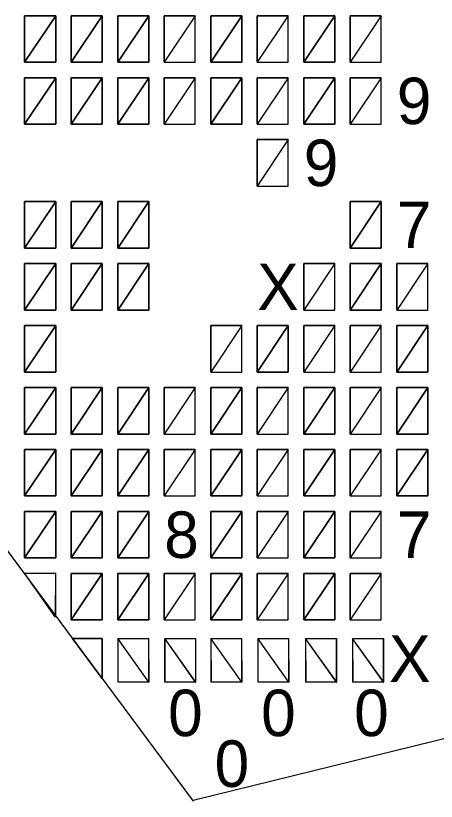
# Model space of a CAD drawing. Extents: x 0 to 34, y -1.2 to 22.
# Drawn here: x 3.4427 to 3.5971, y 4.3379 to 4.6264 of the extents above; entities that cross this region are included whole.
import ezdxf

# ---------------------------------------------------------------- set-up
doc = ezdxf.new("R2010")
doc.units = 0
doc.layers.add('Default', color=7, linetype='Continuous')

msp = doc.modelspace()

# ---------------------------------------------------------------- linework, layer by layer
at = {"layer": 'Default'}
for p, q in [((3.4574, 4.62644), (3.44602, 4.62644)), ((3.44602, 4.62644), (3.44602, 4.60937)), ((3.4574, 4.60937), (3.4574, 4.62644)), ((3.46309, 4.62644), (3.46309, 4.60937)), ((3.47447, 4.62644), (3.46309, 4.62644)), ((3.47447, 4.60937), (3.47447, 4.62644)), ((3.49154, 4.62644), (3.48016, 4.62644)), ((3.48016, 4.62644), (3.48016, 4.60937)), ((3.49154, 4.60937), (3.49154, 4.62644)), ((3.49723, 4.62644), (3.49723, 4.60937)), ((3.50861, 4.62644), (3.49723, 4.62644)), ((3.50861, 4.60937), (3.50861, 4.62644)), ((3.52568, 4.62644), (3.5143, 4.62644)), ((3.5143, 4.62644), (3.5143, 4.60937)), ((3.52568, 4.60937), (3.52568, 4.62644)), ((3.53137, 4.62644), (3.53137, 4.60937)), ((3.54276, 4.62644), (3.53137, 4.62644)), ((3.54276, 4.60937), (3.54276, 4.62644)), ((3.54845, 4.62644), (3.54845, 4.60937)), ((3.55983, 4.62644), (3.54845, 4.62644)), ((3.55983, 4.60937), (3.55983, 4.62644)), ((3.5769, 4.62644), (3.56552, 4.62644)), ((3.56552, 4.62644), (3.56552, 4.60937)), ((3.5769, 4.60937), (3.5769, 4.62644)), ((3.44602, 4.60937), (3.4574, 4.60937)), ((3.46309, 4.60937), (3.47447, 4.60937)), ((3.48016, 4.60937), (3.49154, 4.60937)), ((3.49723, 4.60937), (3.50861, 4.60937)), ((3.5143, 4.60937), (3.52568, 4.60937)), ((3.53137, 4.60937), (3.54276, 4.60937)), ((3.54845, 4.60937), (3.55983, 4.60937)), ((3.56552, 4.60937), (3.5769, 4.60937)), ((3.44602, 4.60368), (3.44602, 4.58661)), ((3.4574, 4.60368), (3.44602, 4.60368)), ((3.4574, 4.58661), (3.4574, 4.60368)), ((3.47447, 4.60368), (3.46309, 4.60368)), ((3.46309, 4.60368), (3.46309, 4.58661)), ((3.47447, 4.58661), (3.47447, 4.60368)), ((3.48016, 4.60368), (3.48016, 4.58661)), ((3.49154, 4.60368), (3.48016, 4.60368)), ((3.49154, 4.58661), (3.49154, 4.60368)), ((3.50861, 4.60368), (3.49723, 4.60368)), ((3.49723, 4.60368), (3.49723, 4.58661)), ((3.50861, 4.58661), (3.50861, 4.60368)), ((3.5143, 4.60368), (3.5143, 4.58661)), ((3.52568, 4.60368), (3.5143, 4.60368)), ((3.52568, 4.58661), (3.52568, 4.60368)), ((3.54276, 4.60368), (3.53137, 4.60368)), ((3.53137, 4.60368), (3.53137, 4.58661)), ((3.54276, 4.58661), (3.54276, 4.60368)), ((3.55983, 4.60368), (3.54845, 4.60368)), ((3.54845, 4.60368), (3.54845, 4.58661)), ((3.55983, 4.58661), (3.55983, 4.60368)), ((3.56552, 4.60368), (3.56552, 4.58661)), ((3.5769, 4.60368), (3.56552, 4.60368)), ((3.5769, 4.58661), (3.5769, 4.60368)), ((3.44602, 4.58661), (3.4574, 4.58661)), ((3.46309, 4.58661), (3.47447, 4.58661)), ((3.48016, 4.58661), (3.49154, 4.58661)), ((3.49723, 4.58661), (3.50861, 4.58661)), ((3.5143, 4.58661), (3.52568, 4.58661)), ((3.53137, 4.58661), (3.54276, 4.58661)), ((3.54845, 4.58661), (3.55983, 4.58661)), ((3.56552, 4.58661), (3.5769, 4.58661)), ((3.54276, 4.58092), (3.53137, 4.58092)), ((3.53137, 4.58092), (3.53137, 4.56385)), ((3.54276, 4.56385), (3.54276, 4.58092)), ((3.53137, 4.56385), (3.54276, 4.56385)), ((3.44602, 4.55816), (3.44602, 4.54109)), ((3.4574, 4.55816), (3.44602, 4.55816)), ((3.4574, 4.54109), (3.4574, 4.55816)), ((3.47447, 4.55816), (3.46309, 4.55816)), ((3.46309, 4.55816), (3.46309, 4.54109)), ((3.47447, 4.54109), (3.47447, 4.55816)), ((3.48016, 4.55816), (3.48016, 4.54109)), ((3.49154, 4.55816), (3.48016, 4.55816)), ((3.49154, 4.54109), (3.49154, 4.55816)), ((3.5769, 4.55816), (3.56552, 4.55816)), ((3.56552, 4.55816), (3.56552, 4.54109)), ((3.5769, 4.54109), (3.5769, 4.55816)), ((3.34772, 4.55371), (3.50785, 4.3379)), ((3.44602, 4.54109), (3.4574, 4.54109)), ((3.46309, 4.54109), (3.47447, 4.54109)), ((3.48016, 4.54109), (3.49154, 4.54109)), ((3.56552, 4.54109), (3.5769, 4.54109)), ((3.44602, 4.53539), (3.44602, 4.51832)), ((3.4574, 4.53539), (3.44602, 4.53539)), ((3.4574, 4.51832), (3.4574, 4.53539)), ((3.46309, 4.53539), (3.46309, 4.51832)), ((3.47447, 4.53539), (3.46309, 4.53539)), ((3.47447, 4.51832), (3.47447, 4.53539)), ((3.49154, 4.53539), (3.48016, 4.53539)), ((3.48016, 4.53539), (3.48016, 4.51832)), ((3.49154, 4.51832), (3.49154, 4.53539)), ((3.54845, 4.53539), (3.54845, 4.51832)), ((3.55983, 4.53539), (3.54845, 4.53539)), ((3.55983, 4.51832), (3.55983, 4.53539)), ((3.56552, 4.53539), (3.56552, 4.51832)), ((3.5769, 4.53539), (3.56552, 4.53539)), ((3.5769, 4.51832), (3.5769, 4.53539)), ((3.59397, 4.53539), (3.58259, 4.53539)), ((3.58259, 4.53539), (3.58259, 4.51832)), ((3.59397, 4.51832), (3.59397, 4.53539)), ((3.44602, 4.51832), (3.4574, 4.51832)), ((3.46309, 4.51832), (3.47447, 4.51832)), ((3.48016, 4.51832), (3.49154, 4.51832)), ((3.54845, 4.51832), (3.55983, 4.51832)), ((3.56552, 4.51832), (3.5769, 4.51832)), ((3.58259, 4.51832), (3.59397, 4.51832)), ((3.4574, 4.51263), (3.44602, 4.51263)), ((3.44602, 4.51263), (3.44602, 4.49556)), ((3.4574, 4.49556), (3.4574, 4.51263)), ((3.52568, 4.51263), (3.5143, 4.51263)), ((3.5143, 4.51263), (3.5143, 4.49556)), ((3.52568, 4.49556), (3.52568, 4.51263)), ((3.54276, 4.51263), (3.53137, 4.51263)), ((3.53137, 4.51263), (3.53137, 4.49556)), ((3.54276, 4.49556), (3.54276, 4.51263)), ((3.54845, 4.51263), (3.54845, 4.49556)), ((3.55983, 4.51263), (3.54845, 4.51263)), ((3.55983, 4.49556), (3.55983, 4.51263)), ((3.56552, 4.51263), (3.56552, 4.49556)), ((3.5769, 4.51263), (3.56552, 4.51263)), ((3.5769, 4.49556), (3.5769, 4.51263)), ((3.58259, 4.51263), (3.58259, 4.49556)), ((3.59397, 4.51263), (3.58259, 4.51263)), ((3.59397, 4.49556), (3.59397, 4.51263)), ((3.44602, 4.49556), (3.4574, 4.49556)), ((3.5143, 4.49556), (3.52568, 4.49556)), ((3.53137, 4.49556), (3.54276, 4.49556)), ((3.54845, 4.49556), (3.55983, 4.49556)), ((3.56552, 4.49556), (3.5769, 4.49556)), ((3.58259, 4.49556), (3.59397, 4.49556)), ((3.4574, 4.48987), (3.44602, 4.48987)), ((3.44602, 4.48987), (3.44602, 4.4728)), ((3.4574, 4.4728), (3.4574, 4.48987)), ((3.46309, 4.48987), (3.46309, 4.4728)), ((3.47447, 4.48987), (3.46309, 4.48987)), ((3.47447, 4.4728), (3.47447, 4.48987)), ((3.49154, 4.48987), (3.48016, 4.48987)), ((3.48016, 4.48987), (3.48016, 4.4728)), ((3.49154, 4.4728), (3.49154, 4.48987)), ((3.49723, 4.48987), (3.49723, 4.4728)), ((3.50861, 4.48987), (3.49723, 4.48987)), ((3.50861, 4.4728), (3.50861, 4.48987)), ((3.52568, 4.48987), (3.5143, 4.48987)), ((3.5143, 4.48987), (3.5143, 4.4728)), ((3.52568, 4.4728), (3.52568, 4.48987)), ((3.53137, 4.48987), (3.53137, 4.4728)), ((3.54276, 4.48987), (3.53137, 4.48987)), ((3.54276, 4.4728), (3.54276, 4.48987)), ((3.54845, 4.48987), (3.54845, 4.4728)), ((3.55983, 4.48987), (3.54845, 4.48987)), ((3.55983, 4.4728), (3.55983, 4.48987)), ((3.5769, 4.48987), (3.56552, 4.48987)), ((3.56552, 4.48987), (3.56552, 4.4728)), ((3.5769, 4.4728), (3.5769, 4.48987)), ((3.59397, 4.48987), (3.58259, 4.48987)), ((3.58259, 4.48987), (3.58259, 4.4728)), ((3.59397, 4.4728), (3.59397, 4.48987)), ((3.44602, 4.4728), (3.4574, 4.4728)), ((3.46309, 4.4728), (3.47447, 4.4728)), ((3.48016, 4.4728), (3.49154, 4.4728)), ((3.49723, 4.4728), (3.50861, 4.4728)), ((3.5143, 4.4728), (3.52568, 4.4728)), ((3.53137, 4.4728), (3.54276, 4.4728)), ((3.54845, 4.4728), (3.55983, 4.4728)), ((3.56552, 4.4728), (3.5769, 4.4728)), ((3.58259, 4.4728), (3.59397, 4.4728)), ((3.44602, 4.46711), (3.44602, 4.45004)), ((3.4574, 4.46711), (3.44602, 4.46711)), ((3.4574, 4.45004), (3.4574, 4.46711)), ((3.47447, 4.46711), (3.46309, 4.46711)), ((3.46309, 4.46711), (3.46309, 4.45004)), ((3.47447, 4.45004), (3.47447, 4.46711)), ((3.48016, 4.46711), (3.48016, 4.45004)), ((3.49154, 4.46711), (3.48016, 4.46711)), ((3.49154, 4.45004), (3.49154, 4.46711)), ((3.50861, 4.46711), (3.49723, 4.46711)), ((3.49723, 4.46711), (3.49723, 4.45004)), ((3.50861, 4.45004), (3.50861, 4.46711)), ((3.5143, 4.46711), (3.5143, 4.45004)), ((3.52568, 4.46711), (3.5143, 4.46711)), ((3.52568, 4.45004), (3.52568, 4.46711)), ((3.54276, 4.46711), (3.53137, 4.46711)), ((3.53137, 4.46711), (3.53137, 4.45004)), ((3.54276, 4.45004), (3.54276, 4.46711)), ((3.55983, 4.46711), (3.54845, 4.46711)), ((3.54845, 4.46711), (3.54845, 4.45004)), ((3.55983, 4.45004), (3.55983, 4.46711)), ((3.56552, 4.46711), (3.56552, 4.45004)), ((3.5769, 4.46711), (3.56552, 4.46711)), ((3.5769, 4.45004), (3.5769, 4.46711)), ((3.58259, 4.46711), (3.58259, 4.45004)), ((3.59397, 4.46711), (3.58259, 4.46711)), ((3.59397, 4.45004), (3.59397, 4.46711)), ((3.44602, 4.45004), (3.4574, 4.45004)), ((3.46309, 4.45004), (3.47447, 4.45004)), ((3.48016, 4.45004), (3.49154, 4.45004)), ((3.49723, 4.45004), (3.50861, 4.45004)), ((3.5143, 4.45004), (3.52568, 4.45004)), ((3.53137, 4.45004), (3.54276, 4.45004)), ((3.54845, 4.45004), (3.55983, 4.45004)), ((3.56552, 4.45004), (3.5769, 4.45004)), ((3.58259, 4.45004), (3.59397, 4.45004)), ((3.4574, 4.44435), (3.44602, 4.44435)), ((3.44602, 4.44435), (3.44602, 4.42728)), ((3.4574, 4.42728), (3.4574, 4.44435)), ((3.46309, 4.44435), (3.46309, 4.42728)), ((3.47447, 4.44435), (3.46309, 4.44435)), ((3.47447, 4.42728), (3.47447, 4.44435)), ((3.49154, 4.44435), (3.48016, 4.44435)), ((3.48016, 4.44435), (3.48016, 4.42728)), ((3.49154, 4.42728), (3.49154, 4.44435)), ((3.52568, 4.44435), (3.5143, 4.44435)), ((3.5143, 4.44435), (3.5143, 4.42728)), ((3.52568, 4.42728), (3.52568, 4.44435)), ((3.53137, 4.44435), (3.53137, 4.42728)), ((3.54276, 4.44435), (3.53137, 4.44435)), ((3.54276, 4.42728), (3.54276, 4.44435)), ((3.54845, 4.44435), (3.54845, 4.42728)), ((3.55983, 4.44435), (3.54845, 4.44435)), ((3.55983, 4.42728), (3.55983, 4.44435)), ((3.5769, 4.44435), (3.56552, 4.44435)), ((3.56552, 4.44435), (3.56552, 4.42728)), ((3.5769, 4.42728), (3.5769, 4.44435)), ((3.44602, 4.42728), (3.4574, 4.42728)), ((3.46309, 4.42728), (3.47447, 4.42728)), ((3.48016, 4.42728), (3.49154, 4.42728)), ((3.5143, 4.42728), (3.52568, 4.42728)), ((3.53137, 4.42728), (3.54276, 4.42728)), ((3.54845, 4.42728), (3.55983, 4.42728)), ((3.56552, 4.42728), (3.5769, 4.42728)), ((3.4574, 4.42159), (3.44602, 4.42159)), ((3.4574, 4.40547), (3.4574, 4.42159)), ((3.47447, 4.42159), (3.46309, 4.42159)), ((3.46309, 4.42159), (3.46309, 4.40452)), ((3.47447, 4.40452), (3.47447, 4.42159)), ((3.48016, 4.42159), (3.48016, 4.40452)), ((3.49154, 4.42159), (3.48016, 4.42159)), ((3.49154, 4.40452), (3.49154, 4.42159)), ((3.50861, 4.42159), (3.49723, 4.42159)), ((3.49723, 4.42159), (3.49723, 4.40452)), ((3.50861, 4.40452), (3.50861, 4.42159)), ((3.5143, 4.42159), (3.5143, 4.40452)), ((3.52568, 4.42159), (3.5143, 4.42159)), ((3.52568, 4.40452), (3.52568, 4.42159)), ((3.54276, 4.42159), (3.53137, 4.42159)), ((3.53137, 4.42159), (3.53137, 4.40452)), ((3.54276, 4.40452), (3.54276, 4.42159)), ((3.55983, 4.42159), (3.54845, 4.42159)), ((3.54845, 4.42159), (3.54845, 4.40452)), ((3.55983, 4.40452), (3.55983, 4.42159)), ((3.56552, 4.42159), (3.56552, 4.40452)), ((3.5769, 4.42159), (3.56552, 4.42159)), ((3.5769, 4.40452), (3.5769, 4.42159)), ((3.46309, 4.40452), (3.47447, 4.40452)), ((3.48016, 4.40452), (3.49154, 4.40452)), ((3.49723, 4.40452), (3.50861, 4.40452)), ((3.5143, 4.40452), (3.52568, 4.40452)), ((3.53137, 4.40452), (3.54276, 4.40452)), ((3.54845, 4.40452), (3.55983, 4.40452)), ((3.56552, 4.40452), (3.5769, 4.40452)), ((3.76865, 4.40245), (3.50784, 4.33819)), ((3.47449, 4.39766), (3.46362, 4.39766)), ((3.47447, 4.38287), (3.47447, 4.39766)), ((3.48016, 4.39766), (3.48016, 4.38175)), ((3.48017, 4.39766), (3.49153, 4.39766)), ((3.49154, 4.38175), (3.49154, 4.39766)), ((3.4974, 4.39766), (3.4974, 4.38175)), ((3.49741, 4.39766), (3.50877, 4.39766)), ((3.50878, 4.38175), (3.50878, 4.39766)), ((3.51433, 4.39766), (3.51433, 4.38175)), ((3.51434, 4.39766), (3.5257, 4.39766)), ((3.52571, 4.38175), (3.52571, 4.39766)), ((3.53157, 4.39766), (3.53157, 4.38175)), ((3.53158, 4.39766), (3.54294, 4.39766)), ((3.54295, 4.38175), (3.54295, 4.39766)), ((3.54913, 4.39766), (3.54913, 4.38175)), ((3.54914, 4.39766), (3.5605, 4.39766)), ((3.56051, 4.38175), (3.56051, 4.39766)), ((3.56637, 4.39766), (3.56637, 4.38175)), ((3.56638, 4.39766), (3.57774, 4.39766)), ((3.57775, 4.38175), (3.57775, 4.39766)), ((3.48016, 4.38175), (3.49154, 4.38175)), ((3.4974, 4.38175), (3.50878, 4.38175)), ((3.51433, 4.38175), (3.52571, 4.38175)), ((3.53157, 4.38175), (3.54295, 4.38175)), ((3.54913, 4.38175), (3.56051, 4.38175)), ((3.56637, 4.38175), (3.57775, 4.38175))]:
    msp.add_line(p, q, dxfattribs=at)
for points in [[(3.4574, 4.62644), (3.4574, 4.60937), (3.44602, 4.60937)], [(3.44602, 4.60937), (3.44602, 4.62644), (3.4574, 4.62644)], [(3.4574, 4.62644), (3.4574, 4.62644), (3.4574, 4.62644)], [(3.47447, 4.62644), (3.47447, 4.60937), (3.46309, 4.60937)], [(3.46309, 4.60937), (3.46309, 4.62644), (3.47447, 4.62644)], [(3.48016, 4.60937), (3.48016, 4.62644), (3.49154, 4.62644)], [(3.49154, 4.62644), (3.49154, 4.60937), (3.48016, 4.60937)], [(3.49723, 4.60937), (3.49723, 4.62644), (3.50861, 4.62644)], [(3.49723, 4.60937), (3.50861, 4.60937), (3.50861, 4.62644)], [(3.5143, 4.60937), (3.5143, 4.62644), (3.52568, 4.62644)], [(3.52568, 4.62644), (3.52568, 4.60937), (3.5143, 4.60937)], [(3.53137, 4.60937), (3.53137, 4.62644), (3.54276, 4.62644)], [(3.53137, 4.60937), (3.54276, 4.60937), (3.54276, 4.62644)], [(3.55983, 4.62644), (3.55983, 4.60937), (3.54845, 4.60937)], [(3.54845, 4.60937), (3.54845, 4.62644), (3.55983, 4.62644)], [(3.56552, 4.60937), (3.5769, 4.60937), (3.5769, 4.62644)], [(3.56552, 4.60937), (3.56552, 4.62644), (3.5769, 4.62644)], [(3.44602, 4.58661), (3.44602, 4.60368), (3.4574, 4.60368)], [(3.4574, 4.60368), (3.4574, 4.58661), (3.44602, 4.58661)], [(3.4574, 4.60368), (3.4574, 4.60368), (3.4574, 4.60368)], [(3.46309, 4.58661), (3.46309, 4.60368), (3.47447, 4.60368)], [(3.47447, 4.60368), (3.47447, 4.58661), (3.46309, 4.58661)], [(3.49154, 4.60368), (3.49154, 4.58661), (3.48016, 4.58661)], [(3.48016, 4.58661), (3.48016, 4.60368), (3.49154, 4.60368)], [(3.49723, 4.58661), (3.50861, 4.58661), (3.50861, 4.60368)], [(3.49723, 4.58661), (3.49723, 4.60368), (3.50861, 4.60368)], [(3.52568, 4.60368), (3.52568, 4.58661), (3.5143, 4.58661)], [(3.5143, 4.58661), (3.5143, 4.60368), (3.52568, 4.60368)], [(3.53137, 4.58661), (3.54276, 4.58661), (3.54276, 4.60368)], [(3.53137, 4.58661), (3.53137, 4.60368), (3.54276, 4.60368)], [(3.54845, 4.58661), (3.54845, 4.60368), (3.55983, 4.60368)], [(3.55983, 4.60368), (3.55983, 4.58661), (3.54845, 4.58661)], [(3.56552, 4.58661), (3.56552, 4.60368), (3.5769, 4.60368)], [(3.56552, 4.58661), (3.5769, 4.58661), (3.5769, 4.60368)], [(3.53137, 4.56385), (3.54276, 4.56385), (3.54276, 4.58092)], [(3.53137, 4.56385), (3.53137, 4.58092), (3.54276, 4.58092)], [(3.44602, 4.54109), (3.44602, 4.55816), (3.4574, 4.55816)], [(3.4574, 4.55816), (3.4574, 4.54109), (3.44602, 4.54109)], [(3.4574, 4.55816), (3.4574, 4.55816), (3.4574, 4.55816)], [(3.46309, 4.54109), (3.46309, 4.55816), (3.47447, 4.55816)], [(3.47447, 4.55816), (3.47447, 4.54109), (3.46309, 4.54109)], [(3.49154, 4.55816), (3.49154, 4.54109), (3.48016, 4.54109)], [(3.48016, 4.54109), (3.48016, 4.55816), (3.49154, 4.55816)], [(3.56552, 4.54109), (3.56552, 4.55816), (3.5769, 4.55816)], [(3.5769, 4.55816), (3.5769, 4.54109), (3.56552, 4.54109)], [(3.44602, 4.51832), (3.44602, 4.53539), (3.4574, 4.53539)], [(3.4574, 4.53539), (3.4574, 4.51832), (3.44602, 4.51832)], [(3.4574, 4.53539), (3.4574, 4.53539), (3.4574, 4.53539)], [(3.47447, 4.53539), (3.47447, 4.51832), (3.46309, 4.51832)], [(3.46309, 4.51832), (3.46309, 4.53539), (3.47447, 4.53539)], [(3.48016, 4.51832), (3.48016, 4.53539), (3.49154, 4.53539)], [(3.49154, 4.53539), (3.49154, 4.51832), (3.48016, 4.51832)], [(3.54845, 4.51832), (3.54845, 4.53539), (3.55983, 4.53539)], [(3.54845, 4.51832), (3.55983, 4.51832), (3.55983, 4.53539)], [(3.5769, 4.53539), (3.5769, 4.51832), (3.56552, 4.51832)], [(3.56552, 4.51832), (3.56552, 4.53539), (3.5769, 4.53539)], [(3.58259, 4.51832), (3.59397, 4.51832), (3.59397, 4.53539)], [(3.58259, 4.51832), (3.58259, 4.53539), (3.59397, 4.53539)], [(3.4574, 4.51263), (3.4574, 4.49556), (3.44602, 4.49556)], [(3.44602, 4.49556), (3.44602, 4.51263), (3.4574, 4.51263)], [(3.4574, 4.51263), (3.4574, 4.51263), (3.4574, 4.51263)], [(3.5143, 4.49556), (3.52568, 4.49556), (3.52568, 4.51263)], [(3.5143, 4.49556), (3.5143, 4.51263), (3.52568, 4.51263)], [(3.53137, 4.49556), (3.53137, 4.51263), (3.54276, 4.51263)], [(3.54276, 4.51263), (3.54276, 4.49556), (3.53137, 4.49556)], [(3.54845, 4.49556), (3.54845, 4.51263), (3.55983, 4.51263)], [(3.54845, 4.49556), (3.55983, 4.49556), (3.55983, 4.51263)], [(3.56552, 4.49556), (3.56552, 4.51263), (3.5769, 4.51263)], [(3.56552, 4.49556), (3.5769, 4.49556), (3.5769, 4.51263)], [(3.59397, 4.51263), (3.59397, 4.49556), (3.58259, 4.49556)], [(3.58259, 4.49556), (3.58259, 4.51263), (3.59397, 4.51263)], [(3.4574, 4.48987), (3.4574, 4.4728), (3.44602, 4.4728)], [(3.44602, 4.4728), (3.44602, 4.48987), (3.4574, 4.48987)], [(3.4574, 4.48987), (3.4574, 4.48987), (3.4574, 4.48987)], [(3.47447, 4.48987), (3.47447, 4.4728), (3.46309, 4.4728)], [(3.46309, 4.4728), (3.46309, 4.48987), (3.47447, 4.48987)], [(3.48016, 4.4728), (3.48016, 4.48987), (3.49154, 4.48987)], [(3.49154, 4.48987), (3.49154, 4.4728), (3.48016, 4.4728)], [(3.49723, 4.4728), (3.49723, 4.48987), (3.50861, 4.48987)], [(3.49723, 4.4728), (3.50861, 4.4728), (3.50861, 4.48987)], [(3.5143, 4.4728), (3.5143, 4.48987), (3.52568, 4.48987)], [(3.52568, 4.48987), (3.52568, 4.4728), (3.5143, 4.4728)], [(3.53137, 4.4728), (3.53137, 4.48987), (3.54276, 4.48987)], [(3.53137, 4.4728), (3.54276, 4.4728), (3.54276, 4.48987)], [(3.55983, 4.48987), (3.55983, 4.4728), (3.54845, 4.4728)], [(3.54845, 4.4728), (3.54845, 4.48987), (3.55983, 4.48987)], [(3.56552, 4.4728), (3.5769, 4.4728), (3.5769, 4.48987)], [(3.56552, 4.4728), (3.56552, 4.48987), (3.5769, 4.48987)], [(3.59397, 4.48987), (3.59397, 4.4728), (3.58259, 4.4728)], [(3.58259, 4.4728), (3.58259, 4.48987), (3.59397, 4.48987)], [(3.59397, 4.48987), (3.59397, 4.48987), (3.59397, 4.48987)], [(3.44602, 4.45004), (3.44602, 4.46711), (3.4574, 4.46711)], [(3.4574, 4.46711), (3.4574, 4.45004), (3.44602, 4.45004)], [(3.4574, 4.46711), (3.4574, 4.46711), (3.4574, 4.46711)], [(3.46309, 4.45004), (3.46309, 4.46711), (3.47447, 4.46711)], [(3.47447, 4.46711), (3.47447, 4.45004), (3.46309, 4.45004)], [(3.49154, 4.46711), (3.49154, 4.45004), (3.48016, 4.45004)], [(3.48016, 4.45004), (3.48016, 4.46711), (3.49154, 4.46711)], [(3.49723, 4.45004), (3.50861, 4.45004), (3.50861, 4.46711)], [(3.49723, 4.45004), (3.49723, 4.46711), (3.50861, 4.46711)], [(3.52568, 4.46711), (3.52568, 4.45004), (3.5143, 4.45004)], [(3.5143, 4.45004), (3.5143, 4.46711), (3.52568, 4.46711)], [(3.53137, 4.45004), (3.54276, 4.45004), (3.54276, 4.46711)], [(3.53137, 4.45004), (3.53137, 4.46711), (3.54276, 4.46711)], [(3.54845, 4.45004), (3.54845, 4.46711), (3.55983, 4.46711)], [(3.55983, 4.46711), (3.55983, 4.45004), (3.54845, 4.45004)], [(3.56552, 4.45004), (3.56552, 4.46711), (3.5769, 4.46711)], [(3.56552, 4.45004), (3.5769, 4.45004), (3.5769, 4.46711)], [(3.58259, 4.45004), (3.58259, 4.46711), (3.59397, 4.46711)], [(3.59397, 4.46711), (3.59397, 4.45004), (3.58259, 4.45004)], [(3.59397, 4.46711), (3.59397, 4.46711), (3.59397, 4.46711)], [(3.4574, 4.44435), (3.4574, 4.42728), (3.44602, 4.42728)], [(3.44602, 4.42728), (3.44602, 4.44435), (3.4574, 4.44435)], [(3.4574, 4.44435), (3.4574, 4.44435), (3.4574, 4.44435)], [(3.47447, 4.44435), (3.47447, 4.42728), (3.46309, 4.42728)], [(3.46309, 4.42728), (3.46309, 4.44435), (3.47447, 4.44435)], [(3.48016, 4.42728), (3.48016, 4.44435), (3.49154, 4.44435)], [(3.49154, 4.44435), (3.49154, 4.42728), (3.48016, 4.42728)], [(3.5143, 4.42728), (3.5143, 4.44435), (3.52568, 4.44435)], [(3.52568, 4.44435), (3.52568, 4.42728), (3.5143, 4.42728)], [(3.53137, 4.42728), (3.53137, 4.44435), (3.54276, 4.44435)], [(3.53137, 4.42728), (3.54276, 4.42728), (3.54276, 4.44435)], [(3.55983, 4.44435), (3.55983, 4.42728), (3.54845, 4.42728)], [(3.54845, 4.42728), (3.54845, 4.44435), (3.55983, 4.44435)], [(3.56552, 4.42728), (3.5769, 4.42728), (3.5769, 4.44435)], [(3.56552, 4.42728), (3.56552, 4.44435), (3.5769, 4.44435)], [(3.45716, 4.4056), (3.44597, 4.42163), (3.45736, 4.42163)], [(3.46309, 4.40452), (3.46309, 4.42159), (3.47447, 4.42159)], [(3.47447, 4.42159), (3.47447, 4.40452), (3.46309, 4.40452)], [(3.49154, 4.42159), (3.49154, 4.40452), (3.48016, 4.40452)], [(3.48016, 4.40452), (3.48016, 4.42159), (3.49154, 4.42159)], [(3.49723, 4.40452), (3.50861, 4.40452), (3.50861, 4.42159)], [(3.49723, 4.40452), (3.49723, 4.42159), (3.50861, 4.42159)], [(3.52568, 4.42159), (3.52568, 4.40452), (3.5143, 4.40452)], [(3.5143, 4.40452), (3.5143, 4.42159), (3.52568, 4.42159)], [(3.53137, 4.40452), (3.54276, 4.40452), (3.54276, 4.42159)], [(3.53137, 4.40452), (3.53137, 4.42159), (3.54276, 4.42159)], [(3.54845, 4.40452), (3.54845, 4.42159), (3.55983, 4.42159)], [(3.55983, 4.42159), (3.55983, 4.40452), (3.54845, 4.40452)], [(3.56552, 4.40452), (3.56552, 4.42159), (3.5769, 4.42159)], [(3.56552, 4.40452), (3.5769, 4.40452), (3.5769, 4.42159)], [(3.46355, 4.39766), (3.47442, 4.39766), (3.47449, 4.38298)], [(3.48024, 4.38182), (3.4916, 4.3817), (3.48017, 4.39766)], [(3.48017, 4.39766), (3.49146, 4.39766), (3.49153, 4.3817)], [(3.49741, 4.39766), (3.5087, 4.39766), (3.50877, 4.3817)], [(3.49748, 4.38182), (3.50884, 4.3817), (3.49741, 4.39766)], [(3.51434, 4.39766), (3.52563, 4.39766), (3.5257, 4.3817)], [(3.51441, 4.38182), (3.52577, 4.3817), (3.51434, 4.39766)], [(3.53165, 4.38182), (3.54301, 4.3817), (3.53158, 4.39766)], [(3.53158, 4.39766), (3.54287, 4.39766), (3.54294, 4.3817)], [(3.54921, 4.38182), (3.56057, 4.3817), (3.54914, 4.39766)], [(3.54914, 4.39766), (3.56043, 4.39766), (3.5605, 4.3817)], [(3.56638, 4.39766), (3.57767, 4.39766), (3.57774, 4.3817)], [(3.56645, 4.38182), (3.57781, 4.3817), (3.56638, 4.39766)], [(3.49153, 4.3817), (3.49153, 4.3817), (3.4916, 4.3817), (3.48024, 4.38182)], [(3.50877, 4.3817), (3.50877, 4.3817), (3.50884, 4.3817), (3.49748, 4.38182)], [(3.5257, 4.3817), (3.5257, 4.3817), (3.52577, 4.3817), (3.51441, 4.38182)], [(3.54294, 4.3817), (3.54294, 4.3817), (3.54301, 4.3817), (3.53165, 4.38182)], [(3.5605, 4.3817), (3.5605, 4.3817), (3.56057, 4.3817), (3.54921, 4.38182)], [(3.57774, 4.3817), (3.57774, 4.3817), (3.57781, 4.3817), (3.56645, 4.38182)]]:
    msp.add_lwpolyline(points, close=True, dxfattribs=at)

# ---------------------------------------------------------------- texts
for s, p in [('9', (3.58259, 4.58661)), ('9', (3.54845, 4.56385)), ('7', (3.58259, 4.54109)), ('X', (3.53137, 4.51832)), ('8', (3.49723, 4.42728)), ('7', (3.58259, 4.42728)), ('X', (3.57974, 4.38175)), ('0', (3.49866, 4.36184)), ('0', (3.5328, 4.36184)), ('0', (3.56694, 4.36184)), ('0', (3.51573, 4.34319))]:
    msp.add_text(s, height=0.01707, dxfattribs=at).set_placement(p)

doc.saveas('drawing.dxf')
